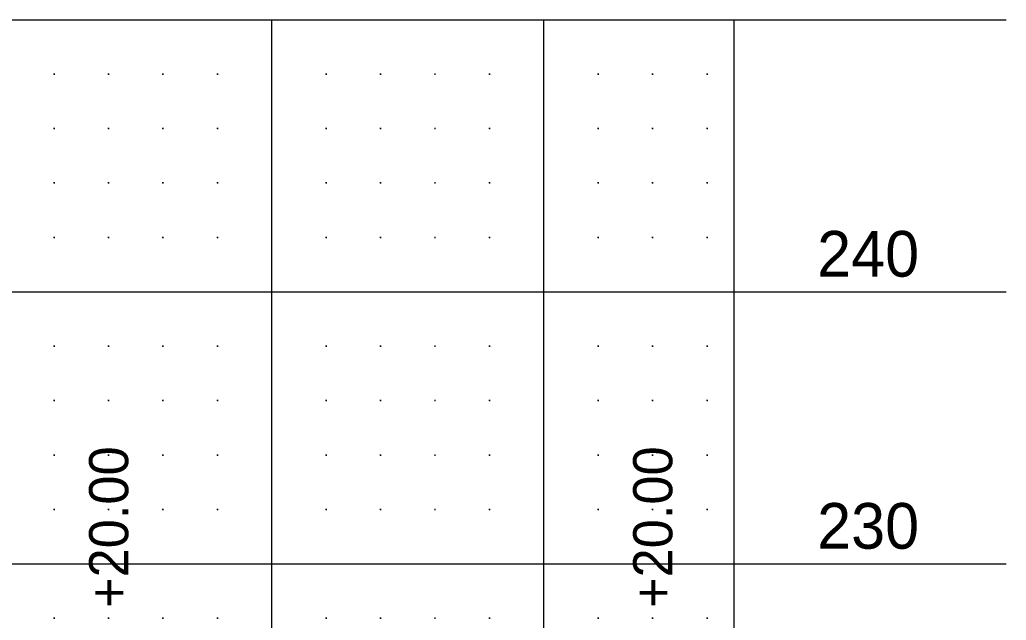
# Model space of a CAD drawing. Extents: x 471 to 2121, y 140 to 650.
# Drawn here: x 1939.7 to 2121.1, y 539.6 to 650 of the extents above; entities that cross this region are included whole.
import ezdxf

# ---------------------------------------------------------------- set-up
doc = ezdxf.new("R2010")
doc.units = 0
for name, color, linetype in [('DSN_DRFT_Border Grid', 7, 'Continuous'), ('DSN_RDWY_Prof Annotation', 7, 'Continuous'), ('Transition Dimensions', 7, 'Continuous')]:
    doc.layers.add(name, color=color, linetype=linetype)

msp = doc.modelspace()

# ---------------------------------------------------------------- linework, layer by layer
at = {"layer": 'DSN_DRFT_Border Grid'}
for p, q in [((521.06, 650), (2071.06, 650)), ((521.06, 650), (2071.06, 650)), ((1986.06, 150), (1986.06, 650)), ((1986.06, 150), (1986.06, 650)), ((2036.06, 150), (2036.06, 650)), ((2036.06, 150), (2036.06, 650)), ((2071.06, 150), (2071.06, 650)), ((2071.06, 150), (2071.06, 650)), ((2071.06, 650), (2121.06, 650)), ((1946.06, 640.12), (1946.06, 639.88)), ((1946.06, 640.12), (1946.06, 639.88)), ((1956.06, 640.12), (1956.06, 639.88)), ((1956.06, 640.12), (1956.06, 639.88)), ((1966.06, 640.12), (1966.06, 639.88)), ((1966.06, 640.12), (1966.06, 639.88)), ((1976.06, 640.12), (1976.06, 639.88)), ((1976.06, 640.12), (1976.06, 639.88)), ((1996.06, 640.12), (1996.06, 639.88)), ((1996.06, 640.12), (1996.06, 639.88)), ((2006.06, 640.12), (2006.06, 639.88)), ((2006.06, 640.12), (2006.06, 639.88)), ((2016.06, 640.12), (2016.06, 639.88)), ((2016.06, 640.12), (2016.06, 639.88)), ((2026.06, 640.12), (2026.06, 639.88)), ((2026.06, 640.12), (2026.06, 639.88)), ((2046.06, 640.12), (2046.06, 639.88)), ((2046.06, 640.12), (2046.06, 639.88)), ((2056.06, 640.12), (2056.06, 639.88)), ((2056.06, 640.12), (2056.06, 639.88)), ((2066.06, 640.12), (2066.06, 639.88)), ((2066.06, 640.12), (2066.06, 639.88)), ((1946.18, 640), (1945.94, 640)), ((1946.18, 640), (1945.94, 640)), ((1956.18, 640), (1955.94, 640)), ((1956.18, 640), (1955.94, 640)), ((1966.18, 640), (1965.94, 640)), ((1966.18, 640), (1965.94, 640)), ((1976.18, 640), (1975.94, 640)), ((1976.18, 640), (1975.94, 640)), ((1996.18, 640), (1995.94, 640)), ((1996.18, 640), (1995.94, 640)), ((2006.18, 640), (2005.94, 640)), ((2006.18, 640), (2005.94, 640)), ((2016.18, 640), (2015.94, 640)), ((2016.18, 640), (2015.94, 640)), ((2026.18, 640), (2025.94, 640)), ((2026.18, 640), (2025.94, 640)), ((2046.18, 640), (2045.94, 640)), ((2046.18, 640), (2045.94, 640)), ((2056.18, 640), (2055.94, 640)), ((2056.18, 640), (2055.94, 640)), ((2066.18, 640), (2065.94, 640)), ((2066.18, 640), (2065.94, 640)), ((1946.18, 630), (1945.94, 630)), ((1946.18, 630), (1945.94, 630)), ((1946.06, 630.12), (1946.06, 629.88)), ((1946.06, 630.12), (1946.06, 629.88)), ((1956.18, 630), (1955.94, 630)), ((1956.18, 630), (1955.94, 630)), ((1956.06, 630.12), (1956.06, 629.88)), ((1956.06, 630.12), (1956.06, 629.88)), ((1966.18, 630), (1965.94, 630)), ((1966.18, 630), (1965.94, 630)), ((1966.06, 630.12), (1966.06, 629.88)), ((1966.06, 630.12), (1966.06, 629.88)), ((1976.18, 630), (1975.94, 630)), ((1976.18, 630), (1975.94, 630)), ((1976.06, 630.12), (1976.06, 629.88)), ((1976.06, 630.12), (1976.06, 629.88)), ((1996.18, 630), (1995.94, 630)), ((1996.18, 630), (1995.94, 630)), ((1996.06, 630.12), (1996.06, 629.88)), ((1996.06, 630.12), (1996.06, 629.88)), ((2006.18, 630), (2005.94, 630)), ((2006.18, 630), (2005.94, 630)), ((2006.06, 630.12), (2006.06, 629.88)), ((2006.06, 630.12), (2006.06, 629.88)), ((2016.18, 630), (2015.94, 630)), ((2016.18, 630), (2015.94, 630)), ((2016.06, 630.12), (2016.06, 629.88)), ((2016.06, 630.12), (2016.06, 629.88)), ((2026.18, 630), (2025.94, 630)), ((2026.18, 630), (2025.94, 630)), ((2026.06, 630.12), (2026.06, 629.88)), ((2026.06, 630.12), (2026.06, 629.88)), ((2046.18, 630), (2045.94, 630)), ((2046.18, 630), (2045.94, 630)), ((2046.06, 630.12), (2046.06, 629.88)), ((2046.06, 630.12), (2046.06, 629.88)), ((2056.18, 630), (2055.94, 630)), ((2056.18, 630), (2055.94, 630)), ((2056.06, 630.12), (2056.06, 629.88)), ((2056.06, 630.12), (2056.06, 629.88)), ((2066.18, 630), (2065.94, 630)), ((2066.18, 630), (2065.94, 630)), ((2066.06, 630.12), (2066.06, 629.88)), ((2066.06, 630.12), (2066.06, 629.88)), ((1946.18, 620), (1945.94, 620)), ((1946.18, 620), (1945.94, 620)), ((1946.06, 620.12), (1946.06, 619.88)), ((1946.06, 620.12), (1946.06, 619.88)), ((1956.18, 620), (1955.94, 620)), ((1956.18, 620), (1955.94, 620)), ((1956.06, 620.12), (1956.06, 619.88)), ((1956.06, 620.12), (1956.06, 619.88)), ((1966.18, 620), (1965.94, 620)), ((1966.18, 620), (1965.94, 620)), ((1966.06, 620.12), (1966.06, 619.88)), ((1966.06, 620.12), (1966.06, 619.88)), ((1976.18, 620), (1975.94, 620)), ((1976.18, 620), (1975.94, 620)), ((1976.06, 620.12), (1976.06, 619.88)), ((1976.06, 620.12), (1976.06, 619.88)), ((1996.18, 620), (1995.94, 620)), ((1996.18, 620), (1995.94, 620)), ((1996.06, 620.12), (1996.06, 619.88)), ((1996.06, 620.12), (1996.06, 619.88)), ((2006.18, 620), (2005.94, 620)), ((2006.18, 620), (2005.94, 620)), ((2006.06, 620.12), (2006.06, 619.88)), ((2006.06, 620.12), (2006.06, 619.88)), ((2016.18, 620), (2015.94, 620)), ((2016.18, 620), (2015.94, 620)), ((2016.06, 620.12), (2016.06, 619.88)), ((2016.06, 620.12), (2016.06, 619.88)), ((2026.18, 620), (2025.94, 620)), ((2026.18, 620), (2025.94, 620)), ((2026.06, 620.12), (2026.06, 619.88)), ((2026.06, 620.12), (2026.06, 619.88)), ((2046.18, 620), (2045.94, 620)), ((2046.18, 620), (2045.94, 620)), ((2046.06, 620.12), (2046.06, 619.88)), ((2046.06, 620.12), (2046.06, 619.88)), ((2056.18, 620), (2055.94, 620)), ((2056.18, 620), (2055.94, 620)), ((2056.06, 620.12), (2056.06, 619.88)), ((2056.06, 620.12), (2056.06, 619.88)), ((2066.18, 620), (2065.94, 620)), ((2066.18, 620), (2065.94, 620)), ((2066.06, 620.12), (2066.06, 619.88)), ((2066.06, 620.12), (2066.06, 619.88)), ((1946.18, 610), (1945.94, 610)), ((1946.18, 610), (1945.94, 610)), ((1946.06, 610.12), (1946.06, 609.88)), ((1946.06, 610.12), (1946.06, 609.88)), ((1956.18, 610), (1955.94, 610)), ((1956.18, 610), (1955.94, 610)), ((1956.06, 610.12), (1956.06, 609.88)), ((1956.06, 610.12), (1956.06, 609.88)), ((1966.18, 610), (1965.94, 610)), ((1966.18, 610), (1965.94, 610)), ((1966.06, 610.12), (1966.06, 609.88)), ((1966.06, 610.12), (1966.06, 609.88)), ((1976.18, 610), (1975.94, 610)), ((1976.18, 610), (1975.94, 610)), ((1976.06, 610.12), (1976.06, 609.88)), ((1976.06, 610.12), (1976.06, 609.88)), ((1996.18, 610), (1995.94, 610)), ((1996.18, 610), (1995.94, 610)), ((1996.06, 610.12), (1996.06, 609.88)), ((1996.06, 610.12), (1996.06, 609.88)), ((2006.18, 610), (2005.94, 610)), ((2006.18, 610), (2005.94, 610)), ((2006.06, 610.12), (2006.06, 609.88)), ((2006.06, 610.12), (2006.06, 609.88)), ((2016.18, 610), (2015.94, 610)), ((2016.18, 610), (2015.94, 610)), ((2016.06, 610.12), (2016.06, 609.88)), ((2016.06, 610.12), (2016.06, 609.88)), ((2026.18, 610), (2025.94, 610)), ((2026.18, 610), (2025.94, 610)), ((2026.06, 610.12), (2026.06, 609.88)), ((2026.06, 610.12), (2026.06, 609.88)), ((2046.18, 610), (2045.94, 610)), ((2046.18, 610), (2045.94, 610)), ((2046.06, 610.12), (2046.06, 609.88)), ((2046.06, 610.12), (2046.06, 609.88)), ((2056.18, 610), (2055.94, 610)), ((2056.18, 610), (2055.94, 610)), ((2056.06, 610.12), (2056.06, 609.88)), ((2056.06, 610.12), (2056.06, 609.88)), ((2066.18, 610), (2065.94, 610)), ((2066.18, 610), (2065.94, 610)), ((2066.06, 610.12), (2066.06, 609.88)), ((2066.06, 610.12), (2066.06, 609.88)), ((521.06, 600), (2071.06, 600)), ((521.06, 600), (2071.06, 600)), ((2071.06, 600), (2121.06, 600)), ((1946.18, 590), (1945.94, 590)), ((1946.18, 590), (1945.94, 590)), ((1946.06, 590.12), (1946.06, 589.88)), ((1946.06, 590.12), (1946.06, 589.88)), ((1956.18, 590), (1955.94, 590)), ((1956.18, 590), (1955.94, 590)), ((1956.06, 590.12), (1956.06, 589.88)), ((1956.06, 590.12), (1956.06, 589.88)), ((1966.18, 590), (1965.94, 590)), ((1966.18, 590), (1965.94, 590)), ((1966.06, 590.12), (1966.06, 589.88)), ((1966.06, 590.12), (1966.06, 589.88)), ((1976.18, 590), (1975.94, 590)), ((1976.18, 590), (1975.94, 590)), ((1976.06, 590.12), (1976.06, 589.88)), ((1976.06, 590.12), (1976.06, 589.88)), ((1996.18, 590), (1995.94, 590)), ((1996.18, 590), (1995.94, 590)), ((1996.06, 590.12), (1996.06, 589.88)), ((1996.06, 590.12), (1996.06, 589.88)), ((2006.18, 590), (2005.94, 590)), ((2006.18, 590), (2005.94, 590)), ((2006.06, 590.12), (2006.06, 589.88)), ((2006.06, 590.12), (2006.06, 589.88)), ((2016.18, 590), (2015.94, 590)), ((2016.18, 590), (2015.94, 590)), ((2016.06, 590.12), (2016.06, 589.88)), ((2016.06, 590.12), (2016.06, 589.88)), ((2026.18, 590), (2025.94, 590)), ((2026.18, 590), (2025.94, 590)), ((2026.06, 590.12), (2026.06, 589.88)), ((2026.06, 590.12), (2026.06, 589.88)), ((2046.18, 590), (2045.94, 590)), ((2046.18, 590), (2045.94, 590)), ((2046.06, 590.12), (2046.06, 589.88)), ((2046.06, 590.12), (2046.06, 589.88)), ((2056.18, 590), (2055.94, 590)), ((2056.18, 590), (2055.94, 590)), ((2056.06, 590.12), (2056.06, 589.88)), ((2056.06, 590.12), (2056.06, 589.88)), ((2066.18, 590), (2065.94, 590)), ((2066.18, 590), (2065.94, 590)), ((2066.06, 590.12), (2066.06, 589.88)), ((2066.06, 590.12), (2066.06, 589.88)), ((1946.18, 580), (1945.94, 580)), ((1946.18, 580), (1945.94, 580)), ((1946.06, 580.12), (1946.06, 579.88)), ((1946.06, 580.12), (1946.06, 579.88)), ((1956.18, 580), (1955.94, 580)), ((1956.18, 580), (1955.94, 580)), ((1956.06, 580.12), (1956.06, 579.88)), ((1956.06, 580.12), (1956.06, 579.88)), ((1966.18, 580), (1965.94, 580)), ((1966.18, 580), (1965.94, 580)), ((1966.06, 580.12), (1966.06, 579.88)), ((1966.06, 580.12), (1966.06, 579.88)), ((1976.18, 580), (1975.94, 580)), ((1976.18, 580), (1975.94, 580)), ((1976.06, 580.12), (1976.06, 579.88)), ((1976.06, 580.12), (1976.06, 579.88)), ((1996.18, 580), (1995.94, 580)), ((1996.18, 580), (1995.94, 580)), ((1996.06, 580.12), (1996.06, 579.88)), ((1996.06, 580.12), (1996.06, 579.88)), ((2006.18, 580), (2005.94, 580)), ((2006.18, 580), (2005.94, 580)), ((2006.06, 580.12), (2006.06, 579.88)), ((2006.06, 580.12), (2006.06, 579.88)), ((2016.18, 580), (2015.94, 580)), ((2016.18, 580), (2015.94, 580)), ((2016.06, 580.12), (2016.06, 579.88)), ((2016.06, 580.12), (2016.06, 579.88)), ((2026.18, 580), (2025.94, 580)), ((2026.18, 580), (2025.94, 580)), ((2026.06, 580.12), (2026.06, 579.88)), ((2026.06, 580.12), (2026.06, 579.88)), ((2046.18, 580), (2045.94, 580)), ((2046.18, 580), (2045.94, 580)), ((2046.06, 580.12), (2046.06, 579.88)), ((2046.06, 580.12), (2046.06, 579.88)), ((2056.18, 580), (2055.94, 580)), ((2056.18, 580), (2055.94, 580)), ((2056.06, 580.12), (2056.06, 579.88)), ((2056.06, 580.12), (2056.06, 579.88)), ((2066.18, 580), (2065.94, 580)), ((2066.18, 580), (2065.94, 580)), ((2066.06, 580.12), (2066.06, 579.88)), ((2066.06, 580.12), (2066.06, 579.88)), ((1946.18, 570), (1945.94, 570)), ((1946.18, 570), (1945.94, 570)), ((1946.06, 570.12), (1946.06, 569.88)), ((1946.06, 570.12), (1946.06, 569.88)), ((1956.18, 570), (1955.94, 570)), ((1956.18, 570), (1955.94, 570)), ((1956.06, 570.12), (1956.06, 569.88)), ((1956.06, 570.12), (1956.06, 569.88)), ((1966.18, 570), (1965.94, 570)), ((1966.18, 570), (1965.94, 570)), ((1966.06, 570.12), (1966.06, 569.88)), ((1966.06, 570.12), (1966.06, 569.88)), ((1976.18, 570), (1975.94, 570)), ((1976.18, 570), (1975.94, 570)), ((1976.06, 570.12), (1976.06, 569.88)), ((1976.06, 570.12), (1976.06, 569.88)), ((1996.18, 570), (1995.94, 570)), ((1996.18, 570), (1995.94, 570)), ((1996.06, 570.12), (1996.06, 569.88)), ((1996.06, 570.12), (1996.06, 569.88)), ((2006.18, 570), (2005.94, 570)), ((2006.18, 570), (2005.94, 570)), ((2006.06, 570.12), (2006.06, 569.88)), ((2006.06, 570.12), (2006.06, 569.88)), ((2016.18, 570), (2015.94, 570)), ((2016.18, 570), (2015.94, 570)), ((2016.06, 570.12), (2016.06, 569.88)), ((2016.06, 570.12), (2016.06, 569.88)), ((2026.18, 570), (2025.94, 570)), ((2026.18, 570), (2025.94, 570)), ((2026.06, 570.12), (2026.06, 569.88)), ((2026.06, 570.12), (2026.06, 569.88)), ((2046.18, 570), (2045.94, 570)), ((2046.18, 570), (2045.94, 570)), ((2046.06, 570.12), (2046.06, 569.88)), ((2046.06, 570.12), (2046.06, 569.88)), ((2056.18, 570), (2055.94, 570)), ((2056.18, 570), (2055.94, 570)), ((2056.06, 570.12), (2056.06, 569.88)), ((2056.06, 570.12), (2056.06, 569.88)), ((2066.18, 570), (2065.94, 570)), ((2066.18, 570), (2065.94, 570)), ((2066.06, 570.12), (2066.06, 569.88)), ((2066.06, 570.12), (2066.06, 569.88)), ((1946.18, 560), (1945.94, 560)), ((1946.18, 560), (1945.94, 560)), ((1946.06, 560.12), (1946.06, 559.88)), ((1946.06, 560.12), (1946.06, 559.88)), ((1956.18, 560), (1955.94, 560)), ((1956.18, 560), (1955.94, 560)), ((1956.06, 560.12), (1956.06, 559.88)), ((1956.06, 560.12), (1956.06, 559.88)), ((1966.18, 560), (1965.94, 560)), ((1966.18, 560), (1965.94, 560)), ((1966.06, 560.12), (1966.06, 559.88)), ((1966.06, 560.12), (1966.06, 559.88)), ((1976.18, 560), (1975.94, 560)), ((1976.18, 560), (1975.94, 560)), ((1976.06, 560.12), (1976.06, 559.88)), ((1976.06, 560.12), (1976.06, 559.88)), ((1996.18, 560), (1995.94, 560)), ((1996.18, 560), (1995.94, 560)), ((1996.06, 560.12), (1996.06, 559.88)), ((1996.06, 560.12), (1996.06, 559.88)), ((2006.18, 560), (2005.94, 560)), ((2006.18, 560), (2005.94, 560)), ((2006.06, 560.12), (2006.06, 559.88)), ((2006.06, 560.12), (2006.06, 559.88)), ((2016.18, 560), (2015.94, 560)), ((2016.18, 560), (2015.94, 560)), ((2016.06, 560.12), (2016.06, 559.88)), ((2016.06, 560.12), (2016.06, 559.88)), ((2026.18, 560), (2025.94, 560)), ((2026.18, 560), (2025.94, 560)), ((2026.06, 560.12), (2026.06, 559.88)), ((2026.06, 560.12), (2026.06, 559.88)), ((2046.18, 560), (2045.94, 560)), ((2046.18, 560), (2045.94, 560)), ((2046.06, 560.12), (2046.06, 559.88)), ((2046.06, 560.12), (2046.06, 559.88)), ((2056.18, 560), (2055.94, 560)), ((2056.18, 560), (2055.94, 560)), ((2056.06, 560.12), (2056.06, 559.88)), ((2056.06, 560.12), (2056.06, 559.88)), ((2066.18, 560), (2065.94, 560)), ((2066.18, 560), (2065.94, 560)), ((2066.06, 560.12), (2066.06, 559.88)), ((2066.06, 560.12), (2066.06, 559.88)), ((521.06, 550), (2071.06, 550)), ((521.06, 550), (2071.06, 550)), ((2071.06, 550), (2121.06, 550)), ((1946.18, 540), (1945.94, 540)), ((1946.18, 540), (1945.94, 540)), ((1946.06, 540.12), (1946.06, 539.88)), ((1946.06, 540.12), (1946.06, 539.88)), ((1956.18, 540), (1955.94, 540)), ((1956.18, 540), (1955.94, 540)), ((1956.06, 540.12), (1956.06, 539.88)), ((1956.06, 540.12), (1956.06, 539.88)), ((1966.18, 540), (1965.94, 540)), ((1966.18, 540), (1965.94, 540)), ((1966.06, 540.12), (1966.06, 539.88)), ((1966.06, 540.12), (1966.06, 539.88)), ((1976.18, 540), (1975.94, 540)), ((1976.18, 540), (1975.94, 540)), ((1976.06, 540.12), (1976.06, 539.88)), ((1976.06, 540.12), (1976.06, 539.88)), ((1996.18, 540), (1995.94, 540)), ((1996.18, 540), (1995.94, 540)), ((1996.06, 540.12), (1996.06, 539.88)), ((1996.06, 540.12), (1996.06, 539.88)), ((2006.18, 540), (2005.94, 540)), ((2006.18, 540), (2005.94, 540)), ((2006.06, 540.12), (2006.06, 539.88)), ((2006.06, 540.12), (2006.06, 539.88)), ((2016.18, 540), (2015.94, 540)), ((2016.18, 540), (2015.94, 540)), ((2016.06, 540.12), (2016.06, 539.88)), ((2016.06, 540.12), (2016.06, 539.88)), ((2026.18, 540), (2025.94, 540)), ((2026.18, 540), (2025.94, 540)), ((2026.06, 540.12), (2026.06, 539.88)), ((2026.06, 540.12), (2026.06, 539.88)), ((2046.18, 540), (2045.94, 540)), ((2046.18, 540), (2045.94, 540)), ((2046.06, 540.12), (2046.06, 539.88)), ((2046.06, 540.12), (2046.06, 539.88)), ((2056.18, 540), (2055.94, 540)), ((2056.18, 540), (2055.94, 540)), ((2056.06, 540.12), (2056.06, 539.88)), ((2056.06, 540.12), (2056.06, 539.88)), ((2066.18, 540), (2065.94, 540)), ((2066.18, 540), (2065.94, 540)), ((2066.06, 540.12), (2066.06, 539.88)), ((2066.06, 540.12), (2066.06, 539.88))]:
    msp.add_line(p, q, dxfattribs=at)

# ---------------------------------------------------------------- texts
at = {"layer": 'DSN_RDWY_Prof Annotation'}
for s, p in [('240', (2086.3, 602.78)), ('240', (2086.3, 602.78)), ('230', (2086.3, 552.78)), ('230', (2086.3, 552.78))]:
    msp.add_text(s, height=8.4, dxfattribs=at).set_placement(p)
at = {"layer": 'Transition Dimensions'}
for p in [(1959.69, 541.88), (2059.69, 541.88)]:
    msp.add_text('+20.00', height=7.2, rotation=90.0268, dxfattribs=at).set_placement(p)

doc.saveas('drawing.dxf')
